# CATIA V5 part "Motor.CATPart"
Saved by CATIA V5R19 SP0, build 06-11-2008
Part number: Motor
Source: Unknown
Bounding box of the stored display mesh (mm): x 48.57 to 110.117, y -30.295 to 30.325, z -70.8 to 31.425
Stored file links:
  D:\Lectures\Catia DMU Lecture Notes\Practice Files\Revolute Joint\Electric Fan\Result\Electric Fan Assembly with No SubAssembly\Motor.CATPart
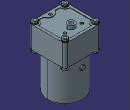
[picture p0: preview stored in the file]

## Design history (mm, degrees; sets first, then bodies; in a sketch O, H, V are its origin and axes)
Body1 "Motor" (main body)
  Solid1: solid without history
